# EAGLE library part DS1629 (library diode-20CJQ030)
Dallas-Maxim's DS1629 2-Wire Digital Thermometer and Real Time Clock Description: The DS1629 2-Wire Digital Thermometer and Real Time Clock integrates the critical functions of a real time clock and a temperature monitor in a small outline 8-pin SOIC package. Communication to the DS1629 is accomplished via a 2-wire interface. The wide power supply range and minimal power requirement of the DS1629 allow for accurate time/temperature measurements in battery-powered applications. The digital thermometer provides 9-bit temperature readings which indicate the temperature of the device. No additional components are required; the device is truly a "temperature-to-digital" converter. The clock/calendar provides seconds, minutes, hours, day, date of the month, day of the week, month, and year. The end of the month date is automatically adjusted for months with less than 31 days, including corrections for leap years. It operates in either a 12- or 24-hour format with AM/PM indicator in 12-hour mode. The crystal oscillator frequency is internally divided, as specified by device configuration. An open-drain output is provided that can be used as the oscillator input for a microcontroller. The open-drain alarm output of the DS1629 will become active when either the measured temperature exceeds the programmed over-temperature limit (TH) or current time reaches the programmed alarm setting. The user can configure which event (time only, temperature only, either, or neither) will generate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
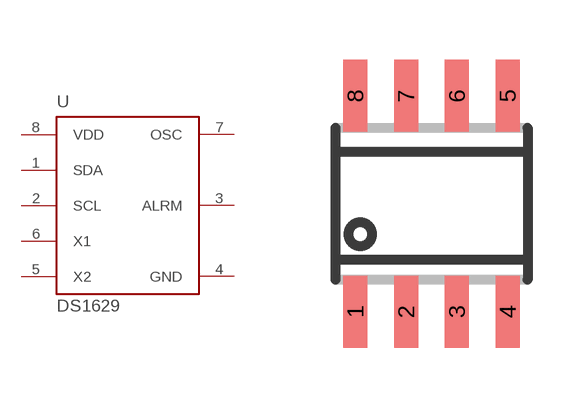
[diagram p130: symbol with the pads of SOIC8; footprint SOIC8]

Designator prefix U

## DS1629  [SOIC8]
1  SDA
2  SCL  in
3  ALRM  out
4  GND  pwr
5  X2  in
6  X1  in
7  OSC  out
8  VDD  pwr

## Footprint SOIC8 (pad centres in mm)
Small Outline IC
smd 0.6 x 1.8: 1 -1.905,-2.7; 2 -0.635,-2.7; 3 0.635,-2.7; 4 1.905,-2.7; 5 1.905,2.7; 6 0.635,2.7; 7 -0.635,2.7; 8 -1.905,2.7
